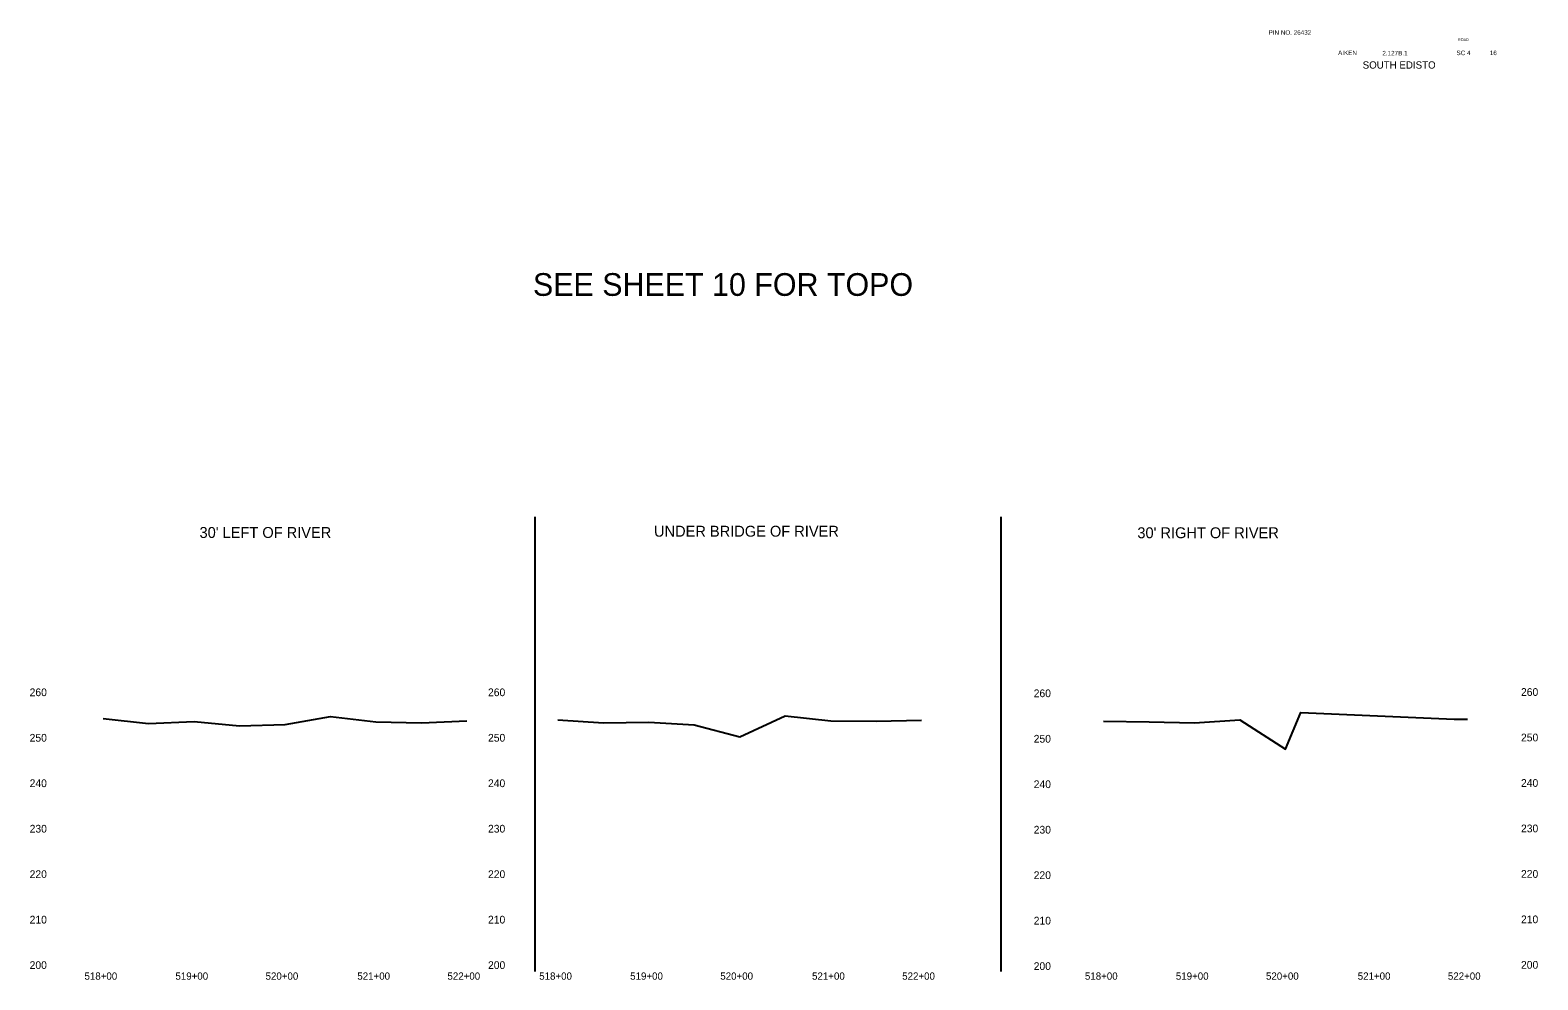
# Model space of a CAD drawing. Extents: x 50163 to 54183, y 54966 to 56011.
# Drawn here: x 50163 to 51821, y 54966 to 56011 of the extents above; entities that cross this region are included whole.
import ezdxf

# ---------------------------------------------------------------- set-up
doc = ezdxf.new("R2010")
doc.units = 0
for name, color, linetype in [('Level 1', 7, 'Continuous'), ('Level 25', 7, 'Continuous'), ('Level 40', 7, 'Continuous'), ('Level 42', 7, 'Continuous'), ('Level 43', 7, 'Continuous')]:
    doc.layers.add(name, color=color, linetype=linetype)

msp = doc.modelspace()

# ---------------------------------------------------------------- linework, layer by layer
at = {"layer": 'Level 1'}
for p, q in [((50718.5, 54975.3), (50718.5, 55475.3)), ((51231.1, 54975.3), (51231.1, 55475.3))]:
    msp.add_line(p, q, dxfattribs=at)
at = {"layer": 'Level 40'}
for points in [[(50243.5, 55253.5), (50293.5, 55248.1), (50343.5, 55250.2), (50393.5, 55245.3), (50443.5, 55247.1), (50493.5, 55255.6), (50543.5, 55249.9), (50593.5, 55248.8), (50643.5, 55250.8)], [(50743.5, 55252), (50793.5, 55248.7), (50843.5, 55249.5), (50893.5, 55246.7), (50943.5, 55233.5), (50993.5, 55256.4), (51043.5, 55251), (51093.5, 55250.6), (51143.5, 55251.8)], [(51343.5, 55250.5), (51393.5, 55249.7), (51443.5, 55248.9), (51493.5, 55251.9), (51543.5, 55220), (51560.5, 55260.3), (51729.2, 55252.7), (51743.5, 55252.8)]]:
    msp.add_lwpolyline(points, dxfattribs=at)

# ---------------------------------------------------------------- texts
at = {"layer": 'Level 1'}
for s, height, p in [('PIN NO. 26432', 5, (51525, 56005.4)), ('ROAD', 3, (51733.2, 55998.5)), ('AIKEN', 5, (51601.4, 55983.1)), ('2.127B.1', 5, (51650.1, 55982.7)), ('SC 4', 5, (51731.6, 55983)), ('16', 5, (51768.2, 55983)), ('SOUTH EDISTO', 8, (51628.4, 55968.2))]:
    msp.add_text(s, height=height, dxfattribs=at).set_placement(p)
at = {"layer": 'Level 25'}
msp.add_text('SEE SHEET 10 FOR TOPO', height=25, dxfattribs=at).set_placement((50716.1, 55718.3))
at = {"layer": 'Level 42'}
for s, height, p in [('260', 8.5, (50162.7, 55278.1)), ('260', 8.5, (50666.7, 55278.1)), ('260', 8.5, (51802.5, 55278.4)), ('260', 8.5, (51266.7, 55277)), ('250', 8.5, (50162.7, 55228.1)), ('250', 8.5, (50666.7, 55228.1)), ('250', 8.5, (51802.5, 55228.4)), ('250', 8.5, (51266.7, 55227)), ('240', 8.5, (51802.5, 55178.4)), ('240', 8.5, (50162.7, 55178.1)), ('240', 8.5, (50666.7, 55178.1)), ('240', 8.5, (51266.7, 55177)), ('230', 8.5, (50162.7, 55128.1)), ('230', 8.5, (50666.7, 55128.1)), ('230', 8.5, (51266.7, 55127)), ('230', 8.5, (51802.5, 55128.4)), ('220', 8.5, (50162.7, 55078.1)), ('220', 8.5, (50666.7, 55078.1)), ('220', 8.5, (51266.7, 55077)), ('220', 8.5, (51802.5, 55078.4)), ('210', 8.5, (50162.7, 55028.1)), ('210', 8.5, (50666.7, 55028.1)), ('210', 8.5, (51266.7, 55027)), ('210', 8.5, (51802.5, 55028.4)), ('200', 8.5, (50162.7, 54978.1)), ('518+00', 8, (50223, 54966.3)), ('519+00', 8, (50323, 54966.3)), ('520+00', 8, (50422.1, 54966.3)), ('521+00', 8, (50523, 54966.3)), ('522+00', 8, (50622.1, 54966.3)), ('200', 8.5, (50666.7, 54978.1)), ('518+00', 8, (50723, 54966.3)), ('519+00', 8, (50823, 54966.3)), ('520+00', 8, (50922.1, 54966.3)), ('521+00', 8, (51023, 54966.3)), ('522+00', 8, (51122.1, 54966.3)), ('200', 8.5, (51266.7, 54977)), ('518+00', 8, (51323, 54966.3)), ('519+00', 8, (51423, 54966.3)), ('520+00', 8, (51522.1, 54966.3)), ('521+00', 8, (51623, 54966.3)), ('522+00', 8, (51722.1, 54966.3)), ('200', 8.5, (51802.5, 54978.4))]:
    msp.add_text(s, height=height, dxfattribs=at).set_placement(p)
at = {"layer": 'Level 43'}
for s, p in [("30' LEFT OF RIVER", (50349.5, 55452.1)), ('UNDER BRIDGE OF RIVER', (50849.2, 55453.5)), ("30' RIGHT OF RIVER", (51380.7, 55451.8))]:
    msp.add_text(s, height=12, dxfattribs=at).set_placement(p)

doc.saveas('drawing.dxf')
